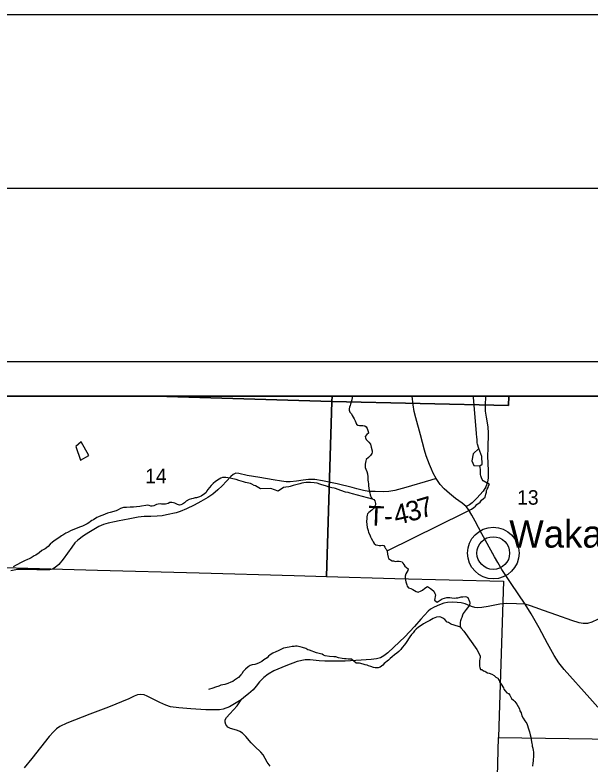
# Model space of a CAD drawing. Extents: x 0 to 34, y 0 to 22.
# Drawn here: x 27.284 to 28.944, y 19.839 to 22 of the extents above; entities that cross this region are included whole.
import ezdxf

# ---------------------------------------------------------------- set-up
doc = ezdxf.new("R2010")
doc.units = 0
for name, color, linetype in [('GM_X_Adjacent_County', 7, 'Continuous'), ('GM_X_County', 7, 'Continuous'), ('GM_X_County_Road', 7, 'Continuous'), ('GM_X_Minor_Lake', 7, 'Continuous'), ('GM_X_Minor_River', 7, 'Continuous'), ('GM_X_Section', 7, 'Continuous'), ('GM_X_Section_Text', 7, 'Continuous'), ('GM_X_State_Route', 7, 'Continuous'), ('GM_X_Township', 7, 'Continuous'), ('GM_X_Township_Road', 7, 'Continuous'), ('GM_X_Township_Road_Text', 7, 'Continuous'), ('GM_X_Unincorporated', 7, 'Continuous'), ('GM_X_Unincorporated_Location', 7, 'Continuous'), ('GM_X_Unincorporated_Text', 7, 'Continuous'), ('SH_Border', 7, 'Continuous'), ('SH_Cut_Line', 7, 'Continuous'), ('SH_Data', 7, 'Continuous')]:
    doc.layers.add(name, color=color, linetype=linetype)

msp = doc.modelspace()

# ---------------------------------------------------------------- linework, layer by layer
at = {"layer": 'GM_X_Adjacent_County'}
msp.add_lwpolyline([(30.8167, 17.8174), (30.8167, 20.9), (24.0167, 20.9), (24.0167, 18.0693)], dxfattribs=at)
at = {"layer": 'GM_X_County'}
msp.add_lwpolyline([(30.8167, 17.8174), (30.8167, 20.9), (24.0167, 20.9), (24.0167, 18.0693)], dxfattribs=at)
at = {"layer": 'GM_X_County_Road'}
for points in [[(28.7571, 20.3003), (28.7322, 20.3012), (28.7023, 20.302), (28.693, 20.3015), (28.6836, 20.3003), (28.6499, 20.2938), (28.6313, 20.2909), (28.6207, 20.29), (28.6119, 20.2904), (28.6022, 20.2934), (28.5905, 20.2986), (28.5832, 20.3013), (28.5719, 20.304), (28.5602, 20.3053), (28.546, 20.3062), (28.5329, 20.3053), (28.522, 20.3026), (28.5098, 20.2981), (28.4943, 20.2911), (28.4839, 20.2857), (28.4764, 20.2798), (28.4556, 20.257), (28.4369, 20.2362), (28.4091, 20.2057), (28.3777, 20.1762), (28.3601, 20.1597), (28.3493, 20.1513), (28.3391, 20.1457), (28.3281, 20.1427), (28.3127, 20.1409), (28.2833, 20.1387), (28.2375, 20.1362), (28.2, 20.1355), (28.1781, 20.1355), (28.1622, 20.137), (28.1359, 20.1393), (28.1217, 20.1396), (28.0989, 20.1344), (28.0657, 20.1226), (28.0316, 20.108), (28.0146, 20.0985), (28.0022, 20.0888), (27.9902, 20.0761), (27.9805, 20.0635), (27.9719, 20.0526), (27.9584, 20.0414), (27.945, 20.031), (27.9367, 20.0245), (27.903, 20.0042), (27.8848, 19.9969), (27.8745, 19.995), (27.8613, 19.995), (27.8353, 19.9955), (27.7919, 19.9982), (27.7573, 20.0012), (27.7334, 20.0042), (27.7191, 20.0091), (27.7022, 20.0162), (27.6656, 20.0349), (27.6566, 20.0384), (27.6471, 20.0397), (27.6381, 20.039), (27.6284, 20.035), (27.6123, 20.0266), (27.5538, 20.0035), (27.4996, 19.983), (27.4339, 19.9567), (27.4131, 19.9471), (27.4039, 19.9404), (27.3951, 19.9323), (27.3831, 19.9185), (27.3324, 19.8553), (27.3108, 19.8283)], [(29.0625, 20.3024), (29.0496, 20.2995), (29.0331, 20.2929), (29.0181, 20.2854), (28.9923, 20.2709), (28.966, 20.2562), (28.9492, 20.2478), (28.9371, 20.2448), (28.9247, 20.2448), (28.9132, 20.2467), (28.8919, 20.2531), (28.8483, 20.268), (28.8098, 20.2823), (28.7859, 20.2905), (28.7722, 20.295), (28.7571, 20.3003)]]:
    msp.add_lwpolyline(points, dxfattribs=at)
at = {"layer": 'GM_X_Minor_Lake'}
for points in [[(27.4748, 20.7683), (27.4593, 20.755), (27.4727, 20.7152)], [(27.4727, 20.7152), (27.4972, 20.7293), (27.4748, 20.7683)], [(28.6233, 20.7492), (28.6063, 20.7337), (28.6029, 20.7136), (28.6087, 20.6999), (28.6261, 20.6988)], [(28.6261, 20.6988), (28.6329, 20.7037), (28.6321, 20.7265), (28.6233, 20.7492)]]:
    msp.add_lwpolyline(points, dxfattribs=at)
at = {"layer": 'GM_X_Minor_River'}
for points in [[(28.2576, 20.9), (28.2576, 20.8961), (28.2561, 20.8901), (28.2542, 20.8844), (28.2523, 20.8775), (28.2512, 20.873), (28.2497, 20.8688), (28.2486, 20.8639), (28.2486, 20.8601), (28.2509, 20.8544), (28.2551, 20.8491), (28.2574, 20.8445), (28.2604, 20.8396), (28.2631, 20.8347), (28.2661, 20.829), (28.2677, 20.8245), (28.2703, 20.8195), (28.2741, 20.8169), (28.2787, 20.8154), (28.2828, 20.8154), (28.2882, 20.8158), (28.2938, 20.8143), (28.298, 20.812), (28.3003, 20.8071), (28.3034, 20.798), (28.3041, 20.7934), (28.3, 20.7896), (28.2947, 20.7839), (28.2955, 20.7801), (28.2977, 20.7752), (28.3019, 20.7714), (28.3057, 20.7672), (28.3099, 20.7619), (28.3126, 20.7528), (28.3149, 20.743), (28.3149, 20.7388), (28.3138, 20.7346), (28.31, 20.7289), (28.3043, 20.7236), (28.2983, 20.7179), (28.2968, 20.7137), (28.296, 20.7088), (28.2953, 20.7039), (28.2946, 20.6986), (28.295, 20.6944), (28.2965, 20.6895), (28.2999, 20.6826), (28.3015, 20.6766), (28.3022, 20.6675), (28.3023, 20.6625), (28.303, 20.6584), (28.3038, 20.6527), (28.305, 20.647), (28.305, 20.6413), (28.3057, 20.6345), (28.3069, 20.6277), (28.3084, 20.6216), (28.3096, 20.6159), (28.3123, 20.6083), (28.3149, 20.6038), (28.3199, 20.6023), (28.3229, 20.5985), (28.3241, 20.5947), (28.3248, 20.5905)], [(28.6233, 20.7492), (28.6195, 20.7614), (28.6187, 20.7652), (28.6183, 20.769), (28.6179, 20.7765), (28.6175, 20.7815), (28.616, 20.7929), (28.6073, 20.8972), (28.6076, 20.9)], [(28.3584, 20.4536), (28.5826, 20.5645), (28.5867, 20.5667), (28.5924, 20.569), (28.5966, 20.5713), (28.6015, 20.5747), (28.609, 20.5789), (28.6132, 20.5831), (28.6177, 20.5873), (28.6272, 20.5945), (28.631, 20.6006), (28.6362, 20.6048), (28.6412, 20.6093), (28.6434, 20.6177), (28.6453, 20.6234), (28.6456, 20.6279), (28.6475, 20.6321), (28.6498, 20.637), (28.6513, 20.6412), (28.6543, 20.645), (28.6353, 20.6556), (28.633, 20.6594), (28.6308, 20.6647), (28.6285, 20.6707), (28.6277, 20.6745), (28.6281, 20.6791), (28.628, 20.6836), (28.6277, 20.6889), (28.6273, 20.6946), (28.6261, 20.6988)], [(28.3166, 20.6033), (28.2581, 20.6181), (28.2516, 20.62), (28.2455, 20.6219), (28.2383, 20.6234), (28.2247, 20.6279), (28.2171, 20.6309), (28.2091, 20.6335), (28.2053, 20.6347), (28.1989, 20.6358), (28.1913, 20.6381), (28.1833, 20.6407), (28.1739, 20.6437), (28.1701, 20.6449), (28.1644, 20.6467), (28.1564, 20.649), (28.1477, 20.6501), (28.1367, 20.6512), (28.1325, 20.6516), (28.125, 20.6512), (28.1178, 20.6504), (28.1121, 20.6493), (28.1064, 20.6478), (28.0867, 20.6428), (28.0788, 20.6398), (28.0742, 20.639), (28.0659, 20.6375), (28.0587, 20.6371), (28.0439, 20.6264), (28.0223, 20.6336), (27.9932, 20.6331), (27.9882, 20.6362), (27.9829, 20.6388), (27.9787, 20.6411), (27.9746, 20.643), (27.9681, 20.6468), (27.9636, 20.6479), (27.9541, 20.6505), (27.9495, 20.6513), (27.9438, 20.6528), (27.9374, 20.6547), (27.9302, 20.6569), (27.923, 20.6596), (27.9131, 20.6622), (27.9048, 20.6633), (27.8983, 20.6648), (27.8923, 20.6652), (27.887, 20.6656), (27.8832, 20.6652), (27.8782, 20.664), (27.8733, 20.6606), (27.8627, 20.6538), (27.8559, 20.6481), (27.8503, 20.6427), (27.8412, 20.6313), (27.8378, 20.6268), (27.8356, 20.6222), (27.8306, 20.6177), (27.8257, 20.6146), (27.8216, 20.612), (27.8163, 20.61), (27.8083, 20.6074), (27.8045, 20.607), (27.7981, 20.6051), (27.7939, 20.6043), (27.7864, 20.602), (27.7777, 20.5971), (27.7731, 20.5925), (27.7678, 20.5883), (27.7629, 20.5864), (27.7591, 20.586), (27.7534, 20.5875), (27.7496, 20.5898), (27.7455, 20.5917), (27.7417, 20.5928), (27.7364, 20.5936), (27.7307, 20.5932), (27.7261, 20.5905), (27.7182, 20.5886), (27.7072, 20.5886), (27.703, 20.5893), (27.6974, 20.5886), (27.6924, 20.5874), (27.6852, 20.584), (27.6803, 20.5832), (27.6761, 20.5832), (27.6712, 20.5844), (27.667, 20.5862), (27.6617, 20.5847), (27.6496, 20.5828), (27.6443, 20.582), (27.6352, 20.5813), (27.6265, 20.5797), (27.6167, 20.5797), (27.6061, 20.5793), (27.6015, 20.5789), (27.597, 20.5789), (27.5883, 20.5762), (27.5822, 20.5724), (27.5758, 20.5698), (27.5591, 20.5644)], [(28.3248, 20.5905), (28.3245, 20.5867), (28.3222, 20.5814), (28.3192, 20.5765), (28.3139, 20.5715), (28.3056, 20.5643), (28.3014, 20.5609), (28.3003, 20.5567), (28.2999, 20.5518), (28.2996, 20.5469), (28.2992, 20.5385), (28.2996, 20.5302), (28.3008, 20.5218), (28.3038, 20.5127), (28.305, 20.5067), (28.3084, 20.5002), (28.31, 20.4949), (28.3119, 20.4904), (28.3157, 20.4843), (28.3176, 20.4801), (28.3206, 20.4752), (28.3259, 20.4714), (28.3312, 20.4703), (28.3358, 20.4699), (28.3403, 20.4696), (28.3449, 20.4703), (28.3491, 20.4696), (28.3521, 20.465), (28.354, 20.4612), (28.3567, 20.4575), (28.3586, 20.4533), (28.3597, 20.4442), (28.3613, 20.4355), (28.3624, 20.4317), (28.3677, 20.4279), (28.3731, 20.4252), (28.3769, 20.4249), (28.3822, 20.4237), (28.386, 20.4238), (28.3932, 20.4238), (28.3977, 20.4234), (28.4019, 20.4226), (28.4038, 20.4185), (28.4068, 20.4147), (28.4099, 20.4101), (28.419, 20.4026), (28.4186, 20.3973), (28.4122, 20.3874), (28.41, 20.3813), (28.41, 20.3753), (28.4115, 20.3699), (28.4119, 20.365), (28.4157, 20.3559), (28.4161, 20.3517), (28.4203, 20.3476), (28.4267, 20.3453), (28.4328, 20.3423), (28.4423, 20.337), (28.4484, 20.3351), (28.4563, 20.3389), (28.4605, 20.3408), (28.4669, 20.3462), (28.4752, 20.3507), (28.4836, 20.3454), (28.4874, 20.3428), (28.4934, 20.3375), (28.4957, 20.3314), (28.498, 20.3273), (28.495, 20.3121), (28.5026, 20.3056), (28.517, 20.3155), (28.5303, 20.319), (28.5397, 20.3197), (28.5454, 20.3182), (28.5526, 20.3179), (28.5579, 20.3183), (28.5621, 20.3187), (28.5663, 20.3194), (28.5719, 20.3209), (28.5772, 20.3217), (28.5837, 20.3221), (28.5878, 20.3217), (28.5916, 20.3191), (28.5962, 20.3077), (28.597, 20.3035), (28.5959, 20.2979), (28.5929, 20.2937), (28.5902, 20.2899), (28.5861, 20.2849), (28.5834, 20.2811), (28.5804, 20.277), (28.5774, 20.2732), (28.5755, 20.2686), (28.5736, 20.2618), (28.5717, 20.2576), (28.5702, 20.2519), (28.5695, 20.2481), (28.5695, 20.2352), (28.5718, 20.2307), (28.5794, 20.2227), (28.6175, 20.1693)], [(27.5591, 20.5644), (27.5512, 20.5625), (27.5375, 20.5572), (27.5319, 20.5553), (27.5247, 20.5522), (27.5201, 20.5503), (27.5103, 20.5435), (27.5061, 20.5412), (27.5016, 20.5385), (27.4967, 20.5347), (27.4921, 20.5324), (27.4785, 20.5252), (27.4698, 20.5221), (27.4536, 20.5153), (27.4464, 20.5126), (27.4358, 20.5069), (27.4305, 20.505), (27.4221, 20.4993), (27.418, 20.4974), (27.4104, 20.4917), (27.3998, 20.4852), (27.3919, 20.4795), (27.3859, 20.4734), (27.3798, 20.467), (27.3715, 20.4601), (27.3617, 20.4548), (27.3537, 20.4483), (27.3439, 20.4415), (27.3397, 20.4396), (27.331, 20.4342), (27.3265, 20.4323), (27.3178, 20.4278), (27.3132, 20.4259), (27.3042, 20.4213), (27.2996, 20.4194), (27.2917, 20.4148), (27.2875, 20.4129), (27.2788, 20.4076)], [(28.5702, 20.2339), (28.5487, 20.2405), (28.5449, 20.2413), (28.5411, 20.2431), (28.5354, 20.2469), (28.5316, 20.2481), (28.5248, 20.2556), (28.5191, 20.2598), (28.513, 20.2628), (28.5084, 20.2639), (28.5005, 20.2624), (28.4914, 20.259), (28.4812, 20.2533), (28.4717, 20.2479), (28.4638, 20.243), (28.4562, 20.2384), (28.4494, 20.2335), (28.4426, 20.2278), (28.4377, 20.2228), (28.4336, 20.2179), (28.429, 20.2122), (28.4241, 20.2058), (28.4136, 20.1898), (28.4087, 20.183), (28.4022, 20.1754), (28.3981, 20.1697), (28.3924, 20.164), (28.3864, 20.1587), (28.38, 20.1537), (28.3728, 20.1484), (28.3671, 20.1438), (28.3622, 20.1385), (28.3501, 20.1286), (28.3459, 20.1244), (28.338, 20.1187), (28.3327, 20.1161), (28.3282, 20.1161), (28.324, 20.1168), (28.3187, 20.1176), (28.3111, 20.1202), (28.305, 20.1221), (28.3005, 20.1244), (28.2948, 20.1255), (28.2895, 20.1274), (28.2785, 20.1296), (28.2732, 20.13), (28.2686, 20.1296), (28.2553, 20.1417), (28.2462, 20.1417), (28.2402, 20.1424), (28.2352, 20.1428), (28.2288, 20.1432), (28.2182, 20.1451), (28.2102, 20.1481), (28.2042, 20.1481), (28.192, 20.1488), (28.1799, 20.151), (28.1746, 20.1533), (28.1704, 20.156), (28.1662, 20.1567), (28.1541, 20.1597), (28.1465, 20.1631), (28.1423, 20.1642), (28.134, 20.1673), (28.1298, 20.1684), (28.1234, 20.1722), (28.1139, 20.1756), (28.1074, 20.1775), (28.1029, 20.1782), (28.0983, 20.1786), (28.0934, 20.1786), (28.0896, 20.1782), (28.0839, 20.1778), (28.0756, 20.1763), (28.0593, 20.1728), (28.0438, 20.1656), (28.0374, 20.1625), (28.0283, 20.1591), (28.0207, 20.1538), (28.0158, 20.15), (28.0124, 20.1458), (28.0022, 20.1397), (27.9962, 20.1348), (27.9886, 20.1306), (27.9826, 20.1279), (27.9761, 20.1264), (27.9685, 20.1248), (27.9625, 20.1229), (27.9576, 20.1195), (27.9496, 20.1131), (27.9417, 20.1047), (27.9394, 20.1005), (27.936, 20.096), (27.9292, 20.0884), (27.9175, 20.0808), (27.913, 20.0769), (27.9073, 20.0747), (27.8986, 20.0712), (27.8899, 20.0686), (27.8782, 20.0663), (27.8721, 20.0632)], [(28.6175, 20.1693), (28.6236, 20.1568), (28.627, 20.15), (28.627, 20.1462), (28.6259, 20.1424), (28.6248, 20.1371), (28.6248, 20.1276), (28.6252, 20.1212), (28.6264, 20.1174), (28.6275, 20.1121), (28.6317, 20.1113), (28.6362, 20.1083), (28.64, 20.1072), (28.6438, 20.1045), (28.6484, 20.1023), (28.6529, 20.1008), (28.6609, 20.0978), (28.667, 20.0943), (28.6723, 20.0894), (28.6776, 20.0864), (28.6818, 20.08), (28.6826, 20.0762), (28.6879, 20.0694), (28.6944, 20.0584), (28.6955, 20.0546), (28.6993, 20.05), (28.7035, 20.0447), (28.7084, 20.0421), (28.7126, 20.0372), (28.7179, 20.0281), (28.7236, 20.0228), (28.7274, 20.019), (28.7328, 20.0114), (28.7404, 19.9982), (28.7412, 19.9929), (28.745, 19.9868), (28.7473, 19.9777), (28.7511, 19.9709), (28.7557, 19.9637), (28.7587, 19.9595), (28.7617, 19.9557), (28.7633, 19.9497), (28.766, 19.9432), (28.769, 19.9323), (28.7717, 19.9228), (28.774, 19.9122), (28.7744, 19.9084), (28.7759, 19.8981), (28.7767, 19.894), (28.7775, 19.8902), (28.7786, 19.8849), (28.7802, 19.878), (28.7809, 19.8739), (28.7813, 19.8693), (28.781, 19.8648), (28.7806, 19.8591), (28.7799, 19.8526), (28.7795, 19.847), (28.7788, 19.8424), (28.7777, 19.8329)], [(27.8721, 20.0632), (27.8626, 20.0605), (27.8551, 20.0579), (27.8426, 20.0544)]]:
    msp.add_lwpolyline(points, dxfattribs=at)
at = {"layer": 'GM_X_Section'}
for p, q in [((27.691, 20.9), (27.1988, 20.9)), ((28.1996, 20.9), (27.691, 20.9)), ((28.7096, 20.9), (28.1996, 20.9)), ((29.18, 20.9), (28.7096, 20.9))]:
    msp.add_line(p, q, dxfattribs=at)
for points in [[(27.1988, 20.9), (27.1828, 20.409), (27.2191, 20.4074), (27.5221, 20.3981), (27.8158, 20.3902), (28.0896, 20.3825), (28.1829, 20.3798), (28.1991, 20.8853), (27.691, 20.9)], [(27.691, 20.9), (28.1991, 20.8853), (28.1996, 20.9)], [(28.7096, 20.9), (28.7088, 20.8738), (28.1991, 20.8853), (28.1829, 20.3798), (28.381, 20.3744), (28.6946, 20.3663), (28.6821, 19.9791), (28.6801, 19.9157), (29.153, 19.9086), (29.18, 20.9)], [(28.1996, 20.9), (28.1991, 20.8853), (28.7088, 20.8738), (28.7096, 20.9)]]:
    msp.add_lwpolyline(points, dxfattribs=at)
msp.add_lwpolyline([(28.6801, 19.9157), (29.153, 19.9086), (29.1334, 18.8778), (28.6533, 18.8853), (28.6686, 19.4646)], close=True, dxfattribs=at)
at = {"layer": 'GM_X_State_Route'}
msp.add_lwpolyline([(28.9669, 20.0027), (28.9436, 20.0289), (28.8691, 20.1114), (28.8541, 20.1308), (28.8402, 20.1519), (28.8213, 20.1866), (28.7971, 20.2316), (28.7741, 20.2723), (28.7571, 20.3003), (28.7164, 20.3599), (28.6896, 20.4003), (28.6781, 20.4207), (28.6688, 20.4365), (28.6315, 20.5033), (28.6121, 20.5396), (28.6028, 20.5573), (28.5934, 20.5731), (28.5867, 20.5815), (28.5752, 20.5916), (28.5558, 20.6055), (28.5386, 20.6193), (28.5228, 20.6327), (28.5116, 20.6454), (28.4998, 20.6624), (28.4914, 20.6782), (28.4861, 20.69), (28.4805, 20.7028), (28.4715, 20.7285), (28.4664, 20.7442), (28.4546, 20.7886), (28.4414, 20.8375), (28.4365, 20.8558), (28.4331, 20.8754), (28.4304, 20.9)], dxfattribs=at)
at = {"layer": 'GM_X_Township'}
msp.add_lwpolyline([(30.8167, 17.8174), (30.8167, 20.9), (26.3564, 20.9)], dxfattribs=at)
at = {"layer": 'GM_X_Township_Road'}
for points in [[(28.6424, 20.9), (28.641, 20.8738), (28.6415, 20.857), (28.6442, 20.8393), (28.6489, 20.8115), (28.6499, 20.7931), (28.6494, 20.7507), (28.6485, 20.7268), (28.6504, 20.6856), (28.6499, 20.6643), (28.6477, 20.6524), (28.6437, 20.6385), (28.636, 20.6265), (28.6169, 20.6057), (28.6042, 20.593), (28.596, 20.5865), (28.5867, 20.5815)], [(28.4998, 20.6624), (28.4847, 20.6579), (28.4126, 20.6367), (28.381, 20.6278), (28.3635, 20.625), (28.3465, 20.6241), (28.3235, 20.625), (28.3052, 20.6256), (28.29, 20.6282), (28.271, 20.6332), (28.2576, 20.6369), (28.2137, 20.6477), (28.1722, 20.6564), (28.1492, 20.6598), (28.1316, 20.6601), (28.1162, 20.6584), (28.0969, 20.6553), (28.0788, 20.6531), (28.0665, 20.6531), (28.0532, 20.6547), (28.0294, 20.6588), (27.9912, 20.6652), (27.9543, 20.6718), (27.9304, 20.6771), (27.9216, 20.6777), (27.9138, 20.6746), (27.9072, 20.6689), (27.8945, 20.6547), (27.8818, 20.6414), (27.8693, 20.6301), (27.8549, 20.618), (27.8405, 20.6083), (27.8208, 20.5966), (27.8011, 20.5862), (27.7792, 20.5757), (27.7605, 20.5673), (27.7494, 20.5636), (27.7213, 20.5576), (27.7084, 20.555), (27.6948, 20.5541), (27.6763, 20.5529), (27.6573, 20.5529), (27.6394, 20.5513), (27.6152, 20.5465), (27.5957, 20.5422), (27.5844, 20.5404), (27.571, 20.5379), (27.5528, 20.5342), (27.5398, 20.5303), (27.5259, 20.5242), (27.5117, 20.5158), (27.4976, 20.5071), (27.4822, 20.4973), (27.4655, 20.485), (27.4569, 20.477), (27.4477, 20.4651), (27.4226, 20.4298), (27.4101, 20.4146), (27.4003, 20.4059), (27.3923, 20.4015), (27.3849, 20.3996), (27.3746, 20.3992), (27.3473, 20.3992), (27.3204, 20.4), (27.3036, 20.4004), (27.2917, 20.4), (27.2724, 20.3963)], [(28.0202, 19.8325), (28.0123, 19.844), (28.0003, 19.8654), (27.9941, 19.8733), (27.9768, 19.8892), (27.9655, 19.9005), (27.9501, 19.9187), (27.9411, 19.9277), (27.9328, 19.933), (27.9261, 19.936), (27.9166, 19.9385), (27.906, 19.9415), (27.8987, 19.9454), (27.8929, 19.9526), (27.8906, 19.9597), (27.8911, 19.9664), (27.895, 19.9729), (27.9044, 19.9839), (27.9254, 20.0068), (27.9367, 20.0245)]]:
    msp.add_lwpolyline(points, dxfattribs=at)
at = {"layer": 'GM_X_Unincorporated'}
for radius in [0.0744, 0.0472]:
    msp.add_circle((28.6648, 20.4476), radius, dxfattribs=at)
at = {"layer": 'GM_X_Unincorporated_Location'}
msp.add_line((28.6648, 20.4476), (28.6648, 20.4476), dxfattribs=at)
at = {"layer": 'SH_Border'}
msp.add_lwpolyline([(2, 21.5), (33.5, 21.5), (33.5, 0.5), (2, 0.5)], close=True, dxfattribs=at)
at = {"layer": 'SH_Cut_Line'}
msp.add_lwpolyline([(0, 0), (34, 0), (34, 22), (0, 22)], close=True, dxfattribs=at)
at = {"layer": 'SH_Data'}
for points in [[(23.9167, 21), (30.9167, 21), (30.9167, 14), (23.9167, 14)], [(24.0167, 20.9), (30.8167, 20.9), (30.8167, 14.1), (24.0167, 14.1)]]:
    msp.add_lwpolyline(points, close=True, dxfattribs=at)

# ---------------------------------------------------------------- texts
at = {"layer": 'GM_X_Section_Text'}
for s, p in [('14', (27.6596, 20.6492)), ('13', (28.7334, 20.5872))]:
    msp.add_text(s, height=0.04186, rotation=0, dxfattribs=at).set_placement(p)
at = {"layer": 'GM_X_Township_Road_Text'}
for s, rotation, p in [('3', 16.1405, (28.422, 20.5371)), ('7', 16.3826, (28.4559, 20.5469)), ('T', 357.9554, (28.3026, 20.5274)), ('4', 12.4855, (28.384, 20.5285)), ('-', 2.9706, (28.3505, 20.5259))]:
    msp.add_text(s, height=0.0568, rotation=rotation, dxfattribs=at).set_placement(p)
at = {"layer": 'GM_X_Unincorporated_Text'}
msp.add_text('Wakatomika', height=0.07898, rotation=0, dxfattribs=at).set_placement((28.7109, 20.4634))

doc.saveas('drawing.dxf')
